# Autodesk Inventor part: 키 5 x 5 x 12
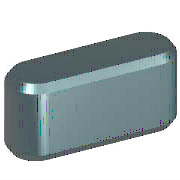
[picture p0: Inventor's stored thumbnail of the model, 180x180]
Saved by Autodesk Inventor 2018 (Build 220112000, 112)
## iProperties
Created: 2012-02
Part Number: 키 5 x 5 x 12
Material: 강철, 연강
Description: 키 및 해당 키홈
Document SubType Name: Modeling
Standard: KS B 1311
Designer: mduedu
Standards Organization: KS
Language: ko-KR
Size Designation: 5 x 5 x 12
Categories: <MemberInstance><Categories><Category DisplayName="샤프트 부품" InternalName="7f7aeb1f-a693-4053-b835-cee3144e0d98" Mnemonic="SHFT"><Category DisplayName="키" Interna
Density: 7.85 g/cm^3
Appearance: 노란색
Mass: 2.10816 g
Surface Area: 2.43471 cm^2
Volume: 0.268556 cm^3
IsCustomPart: 1
Author: mduedu
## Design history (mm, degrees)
workplane "Work Plane1"
workplane "Work Plane2"
sketch "스케치1"
  geometry: L1 (2.5, 2.5)-(9.5, 2.5); L2 (9.5, -2.5)-(2.5, -2.5); L3 (0, 9.4)-(0, -7.4) reference; L4 (-5, 0)-(30, 0) reference; L5 (12, 0)-(12, 7); A1 r 2.5 centre (2.5, 0) between (2.5, 2.5) and (2.5, -2.5); A2 r 2.5 centre (9.5, 0) between (9.5, -2.5) and (9.5, 2.5)
  constraints: 6 end point, 5 point on circle, 4 tangent, 3 point on line, 2 centre point, 1 horizontal, 1 parallel, 1 perpendicular
  dimensions: "d0" = 2.5 radius of A1 (= 0.5 x PB); "d13" = 2.5 radius of A2 (= 0.5 x PB); "d14" = 12 distance between parallel lines of L5 L3 (= NLG)
extrude "본체1" new body sketch "스케치1" taper "d3" = 0 deg; stored distance "d4" = 10
workplane "Work Plane3"
body "Solid1"
chamfer "모따기1" distance "d8" = 0.4 (= PHH); stored, may be unused: second distance "d9" = 0.4 (= PHH), angle "d15" = 45 deg
other parameters: "d1" = -3 (= -PNT), "d2" = 2 (= PH - PNT), "NLG" = 12 [user parameter; used in 3 equation terms], "PB" = 5 [user parameter; used in 2 equation terms], "PNT" = 3 [user parameter; used in 2 equation terms], "PH" = 5 [user parameter; used in 1 equation term], "PHH" = 0.4 [user parameter; used in 2 equation terms], "d10" = 0, "d16" = 0, "d17" = 0, "d18" = 0, "WDMIN" = 12 [user parameter], "PLB2" = 12 (= NLG) [user parameter], "WDMAX" = 17 [user parameter], "PLB1" = 12 (= NLG) [user parameter], "RR" = 0.16 [user parameter], "PUEB" = 2.3 [user parameter]
